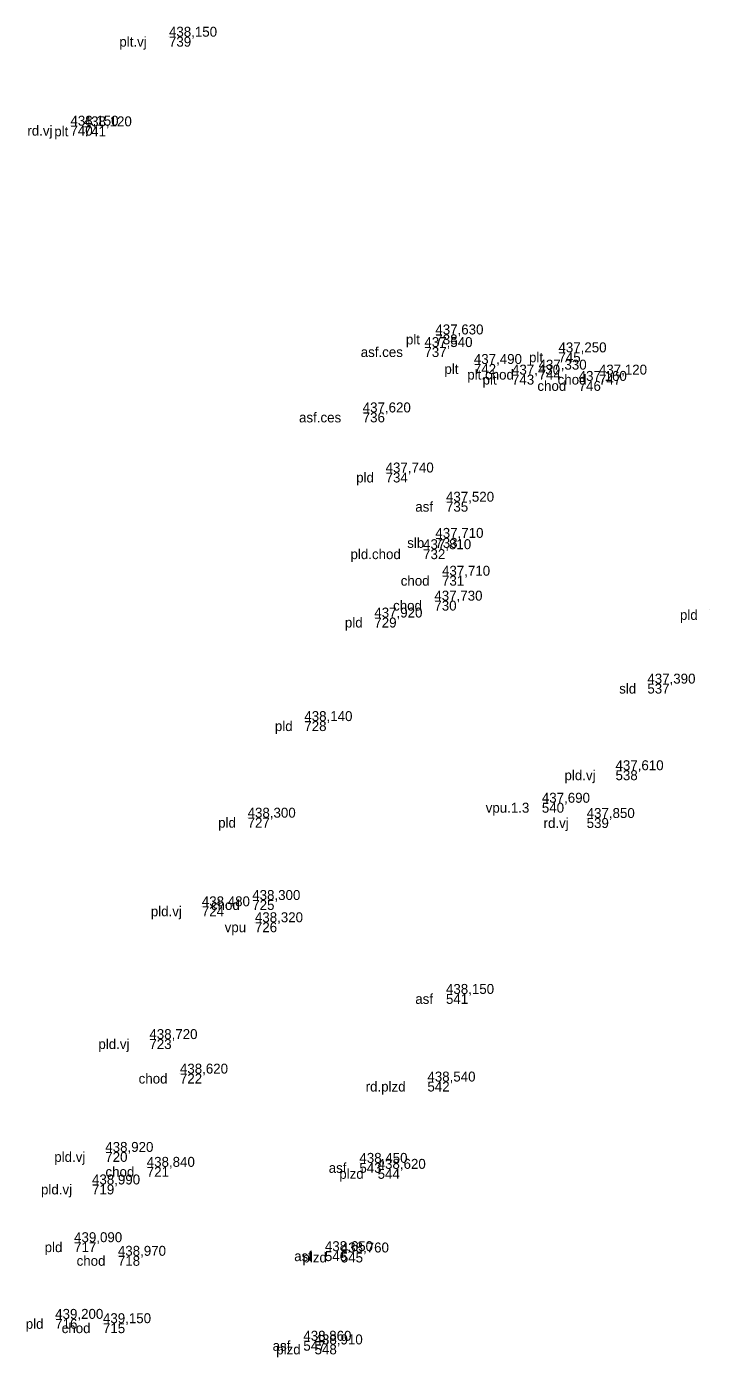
# Model space of a CAD drawing. Extents: x -747136 to -746138, y -1093274 to -1091717.
# Drawn here: x -746687.63 to -746667.05, y -1093079.55 to -1093039.46 of the extents above; entities that cross this region are included whole.
import ezdxf

# ---------------------------------------------------------------- set-up
doc = ezdxf.new("R2010")
doc.units = 0
for name, color, linetype in [('1029', 7, 'Continuous'), ('404', 7, 'Continuous'), ('424', 7, 'Continuous')]:
    doc.layers.add(name, color=color, linetype=linetype)

msp = doc.modelspace()

# ---------------------------------------------------------------- linework, layer by layer
at = {"layer": '404'}
for p, q in [((-746683.34, -1093039.76), (-746683.34, -1093039.76)), ((-746686.31, -1093042.44), (-746686.31, -1093042.44)), ((-746685.91, -1093042.46), (-746685.91, -1093042.46)), ((-746675.31, -1093048.73), (-746675.31, -1093048.73)), ((-746675.64, -1093049.11), (-746675.64, -1093049.11)), ((-746671.6, -1093049.27), (-746671.6, -1093049.27)), ((-746674.15, -1093049.62), (-746674.15, -1093049.62)), ((-746673, -1093049.94), (-746673, -1093049.94)), ((-746672.2, -1093049.79), (-746672.2, -1093049.79)), ((-746670.38, -1093049.94), (-746670.38, -1093049.94)), ((-746670.99, -1093050.13), (-746670.99, -1093050.13)), ((-746677.5, -1093051.08), (-746677.5, -1093051.08)), ((-746676.81, -1093052.89), (-746676.81, -1093052.89)), ((-746674.99, -1093053.77), (-746674.99, -1093053.77)), ((-746675.31, -1093054.86), (-746675.31, -1093054.86)), ((-746675.68, -1093055.2), (-746675.68, -1093055.2)), ((-746675.11, -1093056), (-746675.11, -1093056)), ((-746675.34, -1093056.75), (-746675.34, -1093056.75)), ((-746667.05, -1093057.03), (-746667.05, -1093057.03)), ((-746677.15, -1093057.26), (-746677.15, -1093057.26)), ((-746668.92, -1093059.25), (-746668.92, -1093059.25)), ((-746679.26, -1093060.38), (-746679.26, -1093060.38)), ((-746669.88, -1093061.86), (-746669.88, -1093061.86)), ((-746672.1, -1093062.84), (-746672.1, -1093062.84)), ((-746680.97, -1093063.29), (-746680.97, -1093063.29)), ((-746670.75, -1093063.3), (-746670.75, -1093063.3)), ((-746682.35, -1093065.96), (-746682.35, -1093065.96)), ((-746680.83, -1093065.77), (-746680.83, -1093065.77)), ((-746680.75, -1093066.44), (-746680.75, -1093066.44)), ((-746674.99, -1093068.6), (-746674.99, -1093068.6)), ((-746683.93, -1093069.96), (-746683.93, -1093069.96)), ((-746683.01, -1093071), (-746683.01, -1093071)), ((-746675.55, -1093071.24), (-746675.55, -1093071.24)), ((-746685.26, -1093073.36), (-746685.26, -1093073.36)), ((-746684.01, -1093073.81), (-746684.01, -1093073.81)), ((-746677.6, -1093073.69), (-746677.6, -1093073.69)), ((-746677.05, -1093073.87), (-746677.05, -1093073.87)), ((-746685.66, -1093074.34), (-746685.66, -1093074.34)), ((-746686.2, -1093076.08), (-746686.2, -1093076.08)), ((-746678.64, -1093076.35), (-746678.64, -1093076.35)), ((-746678.16, -1093076.39), (-746678.16, -1093076.39)), ((-746684.88, -1093076.49), (-746684.88, -1093076.49)), ((-746686.77, -1093078.39), (-746686.77, -1093078.39)), ((-746685.33, -1093078.52), (-746685.33, -1093078.52)), ((-746679.29, -1093079.05), (-746679.29, -1093079.05)), ((-746678.95, -1093079.16), (-746678.95, -1093079.16))]:
    msp.add_line(p, q, dxfattribs=at)

# ---------------------------------------------------------------- texts
at = {"layer": '1029'}
for s, p in [('438,150', (-746683.34, -1093039.76)), ('438,150', (-746686.31, -1093042.44)), ('438,120', (-746685.91, -1093042.46)), ('437,630', (-746675.31, -1093048.73)), ('437,540', (-746675.64, -1093049.11)), ('437,250', (-746671.6, -1093049.27)), ('437,490', (-746674.15, -1093049.62)), ('437,330', (-746672.2, -1093049.79)), ('437,430', (-746673, -1093049.94)), ('437,160', (-746670.99, -1093050.13)), ('437,120', (-746670.38, -1093049.94)), ('437,620', (-746677.5, -1093051.08)), ('437,740', (-746676.81, -1093052.89)), ('437,520', (-746674.99, -1093053.77)), ('437,710', (-746675.31, -1093054.86)), ('437,810', (-746675.68, -1093055.2)), ('437,710', (-746675.11, -1093056)), ('437,730', (-746675.34, -1093056.75)), ('437,920', (-746677.15, -1093057.26)), ('437,390', (-746668.92, -1093059.25)), ('438,140', (-746679.26, -1093060.38)), ('437,610', (-746669.88, -1093061.86)), ('437,690', (-746672.1, -1093062.84)), ('438,300', (-746680.97, -1093063.29)), ('437,850', (-746670.75, -1093063.3)), ('438,300', (-746680.83, -1093065.77)), ('438,480', (-746682.35, -1093065.96)), ('438,320', (-746680.75, -1093066.44)), ('438,150', (-746674.99, -1093068.6)), ('438,720', (-746683.93, -1093069.96)), ('438,620', (-746683.01, -1093071)), ('438,540', (-746675.55, -1093071.24)), ('438,920', (-746685.26, -1093073.36)), ('438,840', (-746684.01, -1093073.81)), ('438,450', (-746677.6, -1093073.69)), ('438,620', (-746677.05, -1093073.87)), ('438,990', (-746685.66, -1093074.34)), ('439,090', (-746686.2, -1093076.08)), ('438,970', (-746684.88, -1093076.49)), ('438,650', (-746678.64, -1093076.35)), ('438,760', (-746678.16, -1093076.39)), ('439,200', (-746686.77, -1093078.39)), ('439,150', (-746685.33, -1093078.52)), ('438,860', (-746679.29, -1093079.05)), ('438,910', (-746678.95, -1093079.16))]:
    msp.add_text(s, height=0.3, dxfattribs=at).set_placement(p)
at = {"layer": '424'}
for s, p in [(' plt.vj', (-746684.948, -1093040.06)), ('739', (-746683.34, -1093040.06)), (' rd.vj', (-746687.72, -1093042.74)), (' plt', (-746686.909, -1093042.76)), ('740', (-746686.31, -1093042.74)), ('741', (-746685.91, -1093042.76)), (' plt', (-746676.309, -1093049.03)), ('738', (-746675.31, -1093049.03)), (' asf.ces', (-746677.671, -1093049.41)), ('737', (-746675.64, -1093049.41)), (' plt', (-746672.599, -1093049.57)), ('745', (-746671.6, -1093049.57)), (' plt', (-746675.149, -1093049.92)), (' plt.chod', (-746674.46, -1093050.09)), ('742', (-746674.15, -1093049.92)), (' plt', (-746673.999, -1093050.24)), ('743', (-746673, -1093050.24)), ('744', (-746672.2, -1093050.09)), (' chod', (-746671.736, -1093050.24)), ('747', (-746670.38, -1093050.24)), (' chod', (-746672.346, -1093050.43)), ('746', (-746670.99, -1093050.43)), (' asf.ces', (-746679.531, -1093051.38)), ('736', (-746677.5, -1093051.38)), (' pld', (-746677.809, -1093053.19)), ('734', (-746676.81, -1093053.19)), (' asf', (-746676.027, -1093054.07)), ('735', (-746674.99, -1093054.07)), (' pld.chod', (-746677.98, -1093055.5)), (' slb', (-746676.271, -1093055.16)), ('733', (-746675.31, -1093055.16)), ('732', (-746675.68, -1093055.5)), (' chod', (-746676.466, -1093056.3)), ('731', (-746675.11, -1093056.3)), (' chod', (-746676.696, -1093057.05)), ('730', (-746675.34, -1093057.05)), (' pld', (-746668.049, -1093057.33)), (' pld', (-746678.149, -1093057.56)), ('729', (-746677.15, -1093057.56)), (' sld', (-746669.881, -1093059.55)), ('537', (-746668.92, -1093059.55)), (' pld', (-746680.259, -1093060.68)), ('728', (-746679.26, -1093060.68)), (' pld.vj', (-746671.529, -1093062.16)), ('538', (-746669.88, -1093062.16)), (' vpu.1.3', (-746673.904, -1093063.14)), ('540', (-746672.1, -1093063.14)), (' pld', (-746681.969, -1093063.59)), ('727', (-746680.97, -1093063.59)), (' rd.vj', (-746672.16, -1093063.6)), ('539', (-746670.75, -1093063.6)), (' pld.vj', (-746683.999, -1093066.26)), ('724', (-746682.35, -1093066.26)), (' chod', (-746682.186, -1093066.07)), ('725', (-746680.83, -1093066.07)), (' vpu', (-746681.773, -1093066.74)), ('726', (-746680.75, -1093066.74)), (' asf', (-746676.027, -1093068.9)), ('541', (-746674.99, -1093068.9)), (' pld.vj', (-746685.579, -1093070.26)), ('723', (-746683.93, -1093070.26)), (' chod', (-746684.366, -1093071.3)), ('722', (-746683.01, -1093071.3)), (' rd.plzd', (-746677.524, -1093071.54)), ('542', (-746675.55, -1093071.54)), (' pld.vj', (-746686.909, -1093073.66)), ('720', (-746685.26, -1093073.66)), (' chod', (-746685.366, -1093074.11)), ('721', (-746684.01, -1093074.11)), (' asf', (-746678.637, -1093073.99)), (' plzd', (-746678.318, -1093074.17)), ('543', (-746677.6, -1093073.99)), ('544', (-746677.05, -1093074.17)), (' pld.vj', (-746687.309, -1093074.64)), ('719', (-746685.66, -1093074.64)), (' pld', (-746687.199, -1093076.38)), ('717', (-746686.2, -1093076.38)), (' asf', (-746679.677, -1093076.65)), (' plzd', (-746679.428, -1093076.69)), ('546', (-746678.64, -1093076.65)), ('545', (-746678.16, -1093076.69)), (' chod', (-746686.236, -1093076.79)), ('718', (-746684.88, -1093076.79)), (' pld', (-746687.769, -1093078.69)), ('716', (-746686.77, -1093078.69)), (' chod', (-746686.686, -1093078.82)), ('715', (-746685.33, -1093078.82)), (' asf', (-746680.327, -1093079.35)), (' plzd', (-746680.218, -1093079.46)), ('547', (-746679.29, -1093079.35)), ('548', (-746678.95, -1093079.46))]:
    msp.add_text(s, height=0.3, dxfattribs=at).set_placement(p)

doc.saveas('drawing.dxf')
